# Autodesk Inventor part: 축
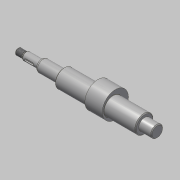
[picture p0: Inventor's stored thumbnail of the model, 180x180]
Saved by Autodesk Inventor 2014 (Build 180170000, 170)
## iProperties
Created: 2015-12
Part Number: 축
Document SubType Name: Modeling
Designer: mdu
Density: 7.86 g/cm^3
Material: 강철, 연강
Appearance: 강철
Mass: 484.678 g
Surface Area: 125.968 cm^2
Volume: 61.6639 cm^3
Author: mdu
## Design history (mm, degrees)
sketch "스케치1"
  geometry: L1 (62, 100.9)-(62, 67.1) reference; L2 (51, 101.2)-(51, 84) reference; L3 (-51, 84)-(-51, 101.2) reference; L4 (-62, 67.1)-(-62, 100.9) reference; L5 (-51.6, 91.5)-(-61.4, 91.5) reference; L6 (51.6, 91.5)-(61.4, 91.5) reference; L7 (67, 84)-(-109, 84); L8 (-77, 64.201)-(-77, 103.799) reference; L9 (67, 84)-(67, 91.5); L10 (67, 91.5)-(51, 91.5); L11 (51, 91.5)-(51, 95.5); L12 (51, 95.5)-(-51, 95.5); L13 (-51, 95.5)-(-51, 91.5); L14 (-51, 91.5)-(-79, 91.5); L15 (-79, 91.5)-(-79, 89); L16 (-79, 89)-(-99, 89); L17 (-99, 89)-(-99, 87); L18 (-100.5, 88)-(-109, 88); L19 (-109, 88)-(-109, 84); L20 (-99, 87)-(-100.5, 87); L21 (-100.5, 87)-(-100.5, 88); 2 further points
  constraints: 32 end point, 7 parallel, 6 point on line, 5 perpendicular, 2 collinear, 2 horizontal, 1 midpoint, 4 other
  dimensions: "d0" = 5 distance from line of L7.start L1; "d2" = 2 distance between parallel lines of L15 L8; "d3" = 23 diameter of L12 L7; "d4" = 10 diameter of L16 L7; "d5" = 1.5 distance of L17.end L20.end; "d6" = 6 diameter of L20 L7; "d7" = 20 distance of L15.end L16.end; "d8" = 10 distance between parallel lines of L17 L19; "d9" = 8 diameter of L18 L7
revolve "회전1" sketch "스케치1" stored, may be unused: angle "d10" = 90 deg
sketch "스케치2"
  geometry: C1 r 11.5 at (84, 0) reference; C2 r 11.5 at (84, 0) reference; C3 r 16.5 at (87, 0); 1 further point
  constraints: 1 centre point, 1 horizontal alignment
  dimensions: "d11" = 33 diameter of C3; "d12" = 3 distance of C3.centre C1.centre
extrude "돌출1" join sketch "스케치2" stored distance "d13" = 22; taper "d14" = 0 deg
chamfer "모따기1" distance "d15" = 1; stored, may be unused: second distance "d16" = 2, angle "d17" = 45 deg
feature "스레드1" dims "d18" = 10, "d19" = 0
node "작업 평면1"
sketch "스케치3"
  geometry: L1 (-5.5, -1.5)-(3.5, -1.5); L2 (3.5, 1.5)-(-5.5, 1.5); L3 (-10, -4)-(-10, 4) reference; A1 r 1.5 centre (3.5, 0) between (3.5, -1.5) and (3.5, 1.5); A2 r 1.5 centre (-5.5, 0) between (-5.5, 1.5) and (-5.5, -1.5); 2 further points
  constraints: 4 end point, 4 point on circle, 4 tangent, 2 centre point, 1 horizontal, 1 horizontal alignment, 1 midpoint, 1 parallel
  dimensions: "d20" = 3 distance between parallel lines of L1 L2; "d21" = 12 dimension on A1 A2; "d22" = 3 distance edge to line of A2 L3
extrude "돌출2" cut sketch "스케치3" distance "d23" = 1.8; taper "d24" = 0 deg
fillet "모깎기1" dims "d25" = 0.3
fillet "모깎기2" dims "d26" = 3
node "솔리드1"
node "참조1"
node "참조2"
node "참조3"
node "참조4"
node "참조5"
node "투영된 루프1"
